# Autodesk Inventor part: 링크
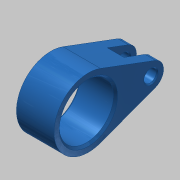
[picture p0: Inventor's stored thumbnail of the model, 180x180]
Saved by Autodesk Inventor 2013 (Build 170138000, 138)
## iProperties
Created: 2016-08
Part Number: 링크
Material: 강철, 탄소
Document SubType Name: Modeling
Designer: mduedu
Density: 7.87 g/cm^3
Mass: 80.4021 g
Surface Area: 54.1946 cm^2
Volume: 10.2163 cm^3
Author: mduedu
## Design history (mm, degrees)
sketch "스케치1"
  geometry: L1 (32.1, 5.62)-(5.775, 15.456); L2 (32.1, -5.62)-(5.775, -15.456); C1 r 13 at (0, 0); C2 r 3 at (30, 0); A1 r 16.5 centre (0, 0) between (5.775, 15.456) and (5.775, -15.456); A2 r 6 centre (30, 0) between (32.1, 5.62) and (32.1, -5.62); 1 further point
  constraints: 4 centre point, 4 end point, 4 point on circle, 4 tangent, 3 coincident, 1 horizontal alignment
  dimensions: "d0" = 33 diameter of A1; "d2" = 12 diameter of A2; "d3" = 30 distance of A2.centre point (0, 0); "d4" = 26 diameter of C1; "d5" = 6 diameter of C2
extrude "돌출1" new body sketch "스케치1" stored distance "d6" = 18; taper "d7" = 0 deg
sketch "스케치2"
  geometry: L1 (-9, 36)-(9, 36) reference; L2 (0, 0)-(0, 36); L3 (-4, 36)-(4, 36); L4 (4, 36)-(4, 22); L5 (4, 22)-(-4, 22); L6 (-4, 22)-(-4, 36)
  constraints: 10 end point, 2 midpoint, 2 parallel, 1 horizontal, 1 perpendicular, 1 point on line
  dimensions: "d8" = 8 distance between parallel lines of L4 L6; "d10" = 14 distance of L3.end L4.end
extrude "돌출2" cut sketch "스케치2" stored distance "d11" = 20; taper "d12" = 0 deg
chamfer "모따기1" distance "d13" = 1; stored, may be unused: second distance "d14" = 2, angle "d15" = 45 deg
chamfer "모따기2" distance "d16" = 0.5; stored, may be unused: second distance "d17" = 2, angle "d18" = 45 deg
node "솔리드1"
